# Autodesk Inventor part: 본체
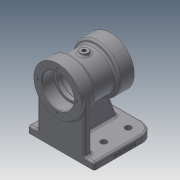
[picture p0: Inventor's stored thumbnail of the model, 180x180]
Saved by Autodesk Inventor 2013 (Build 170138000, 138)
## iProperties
Created: 2020-06
Part Number: 본체
Material: 일반
Document SubType Name: Modeling
Designer: 19
Density: 1 g/cm^3
Mass: 268.673 g
Surface Area: 641.499 cm^2
Volume: 268.673 cm^3
Author: 19
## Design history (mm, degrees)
sketch "스케치2"
  geometry: C1 r 35 at (0, 0); 1 further point
  constraints: 1 centre point, 1 coincident
  dimensions: "d8" = 70 diameter of C1
extrude "돌출1" new body sketch "스케치2" distance "d10" = 22; taper "d11" = 0 deg
sketch "스케치3"
  geometry: C1 r 35 at (0, 0) reference; C2 r 29 at (0, 0)
  constraints: 1 centre point, 1 coincident
  dimensions: "d12" = 29 radius of C2
extrude "돌출2" join sketch "스케치3" distance "d13" = 34; taper "d14" = 0 deg
sketch "스케치4"
  geometry: C1 r 29 at (0, 0) reference; C2 r 35 at (0, 0)
  constraints: 1 centre point, 1 coincident
  dimensions: "d15" = 35 radius of C2
extrude "돌출3" join sketch "스케치4" distance "d16" = 22; taper "d17" = 0 deg
sketch "스케치5"
  geometry: C1 r 35 at (0, 0) reference; C2 r 23.5 at (0, 0)
  constraints: 1 centre point, 1 coincident
  dimensions: "d18" = 47 diameter of C2
extrude "돌출4" cut sketch "스케치5" distance "d20" = 18; taper "d21" = 0 deg
sketch "스케치6"
  geometry: C1 r 23.5 at (0, 0) reference; C2 r 20 at (0, 0)
  constraints: 1 centre point, 1 coincident
  dimensions: "d22" = 20 radius of C2
extrude "돌출5" cut sketch "스케치6" distance "d23" = 6; taper "d24" = 0 deg
sketch "스케치7"
  geometry: C1 r 20 at (0, 0) reference; C2 r 23 at (0, 0)
  constraints: 1 centre point, 1 coincident
  dimensions: "d25" = 46 diameter of C2
extrude "돌출6" cut sketch "스케치7" distance "d27" = 30; taper "d28" = 0 deg
sketch "스케치8"
  geometry: C1 r 35 at (0, 0) reference; C2 r 23.5 at (0, 0)
  constraints: 1 centre point, 1 coincident
  dimensions: "d29" = 47 diameter of C2
extrude "돌출7" cut sketch "스케치8" distance "d31" = 18; taper "d32" = 0 deg
sketch "스케치9"
  geometry: C1 r 23.5 at (0, 0) reference; C2 r 20 at (0, 0)
  constraints: 1 centre point, 1 coincident
  dimensions: "d33" = 20 radius of C2
extrude "돌출8" cut sketch "스케치9" distance "d34" = 6; taper "d35" = 0 deg
node "작업 평면2"
  node "작업 평면1"
sketch "스케치10"
  geometry: L1 (14.177, 34)-(-14.177, 34) reference; L2 (-14.177, 34)-(-14.177, 56) reference; L3 (-14.177, 56)-(14.177, 56) reference; L4 (14.177, 56)-(14.177, 34) reference; L5 (-14.177, -22)-(-14.177, 0) reference; L6 (-14.177, 0)-(14.177, 0) reference; L7 (14.177, 0)-(14.177, -22) reference; L8 (14.177, -22)-(-14.177, -22) reference; C1 r 6 at (0, 17); 2 further points
  constraints: 1 centre point, 1 midpoint, 1 vertical alignment
  dimensions: "d41" = 12 diameter of C1; "d42" = 39 distance from line of L3 C1.centre
extrude "돌출9" join sketch "스케치10" stored distance "d43" = 3; taper "d44" = 0 deg
sketch "스케치11"
  geometry: C1 r 6 at (0, 0) reference; 1 further point
hole "구멍1" sketch "스케치11" at (0, 0) diameter "d45" = 5.188; stored, may be unused: countersink angle "d49" = 90 deg, drill point angle "d51" = 118 deg; dims "d46" = 30, "d47" = 4, "d48" = 2, "d50" = 8
node "작업 평면3"
sketch "스케치12"
  geometry: L1 (49, 73)-(-49, 73); L2 (-49, 73)-(-49, -17); L3 (-49, -17)-(49, -17); L4 (49, -17)-(49, 73); L5 (35, 78)-(-35, 78) reference; L6 (-35, 0)-(35, 0) reference; 5 further points
  constraints: 8 end point, 4 midpoint, 2 parallel, 2 vertical alignment, 1 horizontal, 1 perpendicular
  dimensions: "d53" = 5 distance between parallel lines of L1 L5; "d54" = 90 distance of L3.end L1.start; "d55" = 98 distance of L2.end L3.end
extrude "돌출10" join sketch "스케치12" distance "d56" = 10; taper "d57" = 0 deg
sketch "스케치13"
  geometry: L1 (-49, -73)-(49, -73) reference; L2 (-35, -63)-(35, -63); L3 (35, -63)-(35, -73); L4 (35, -73)-(-35, -73); L5 (-35, -73)-(-35, -63); 3 further points
  constraints: 8 end point, 3 midpoint, 2 parallel, 1 horizontal, 1 perpendicular, 1 vertical alignment
  dimensions: "d58" = 10 distance of L2.end L3.end; "d60" = 70 distance of L2.start L2.end
extrude "돌출11" join sketch "스케치13" stored distance "d61" = 10; taper "d62" = 0 deg
sketch "스케치14"
  geometry: L1 (-35, -63)-(35, -63) reference; L2 (49, 17)-(-49, 17) reference; L3 (-5, 5)-(5, 5); L4 (5, 5)-(5, -63); L5 (5, -63)-(-5, -63); L6 (-5, -63)-(-5, 5); 3 further points
  constraints: 8 end point, 3 midpoint, 2 parallel, 1 horizontal, 1 perpendicular, 1 vertical alignment
  dimensions: "d63" = 12 distance between parallel lines of L3 L2; "d64" = 10 distance of L3.start L3.end
extrude "돌출12" join sketch "스케치14" stored distance "d66" = 10; taper "d67" = 0 deg
feature "면 기울기1" dims angle "d68" = 20 deg
sketch "스케치15"
  geometry: L1 (0, 28.5)-(0, 0); L2 (0, 0)-(28.5, 0); L3 (-28.5, 0)-(0, 0); L4 (0, -28.5)-(0, 0); C1 r 35 at (0, 0) reference; A1 r 28.5 centre (0, 0) between (0, 28.5) and (28.5, 0)
  constraints: 8 end point, 4 point on circle, 2 perpendicular, 1 centre point, 1 coincident, 1 collinear, 1 vertical
  dimensions: "d69" = 57 diameter of A1
hole "구멍2" sketch "스케치15" at (0, 28.5), (28.5, 0), (-28.5, 0), (0, -28.5) diameter "d71" = 3.242; stored, may be unused: countersink angle "d75" = 90 deg, drill point angle "d77" = 118 deg; dims "d72" = 10, "d73" = 4, "d74" = 2, "d76" = 12
sketch "스케치16"
  geometry: L1 (0, 0)-(0, 28.5); L2 (0, 0)-(28.5, 0); L3 (0, 0)-(0, -28.5); L4 (0, 0)-(-28.5, 0); C1 r 23.5 at (0, 0) reference; A1 r 28.5 centre (0, 0) between (0, 28.5) and (28.5, 0)
  constraints: 8 end point, 4 point on circle, 3 perpendicular, 1 centre point, 1 coincident, 1 vertical
  dimensions: "d78" = 57 diameter of A1
hole "구멍3" sketch "스케치16" at (0, 28.5), (28.5, 0), (0, -28.5), (-28.5, 0) diameter "d80" = 3.242; stored, may be unused: countersink angle "d84" = 90 deg, drill point angle "d86" = 118 deg; dims "d81" = 10, "d82" = 4, "d83" = 2, "d85" = 12
sketch "스케치18"
  geometry: L1 (0, 0)-(90, 0) reference; L2 (0, 0)-(0, 10) reference; 2 further points
  constraints: 1 other
  dimensions: "d87" = 4 distance from line of L1 point (45, 4); "d88" = 45 distance from line of point (45, 4) L2
feature "엠보싱1" sketch "스케치18" dims "d8" = 70, "d89" = 0.5, "d90" = 0
chamfer "모따기1" distance "d91" = 1; stored, may be unused: second distance "d92" = 2, angle "d93" = 45 deg
fillet "모깎기1" dims "d94" = 0.3
fillet "모깎기2" dims "d95" = 3
fillet "모깎기3" dims "d96" = 3
fillet "모깎기4" dims "d97" = 3
fillet "모깎기5" dims "d98" = 3
fillet "모깎기6" dims "d99" = 20
fillet "모깎기7" dims "d100" = 3
fillet "모깎기8" dims "d101" = 3
fillet "모깎기9" dims "d102" = 3
fillet "모깎기10" dims "d103" = 3
fillet "모깎기11" dims "d104" = 3
fillet "모깎기12" dims "d105" = 3
sketch "스케치19"
  geometry: L1 (-46, -70)-(-46, -3) reference; L2 (-29, -3)-(-29, -39); L3 (29, -3)-(29, -39); C1 r 4.5 at (-29, -3); C2 r 4.5 at (29, -3); C3 r 4.5 at (-29, -39); C4 r 4.5 at (29, -39); A1 r 17 centre (29, -3) between (46, -3) and (29, 14) reference; A2 r 17 centre (-29, -3) between (-29, 14) and (-46, -3) reference; 1 further point
  constraints: 4 centre point, 4 coincident, 4 end point, 2 parallel
  dimensions: "d106" = 4.5 radius of C1; "d107" = 4.5 radius of C2; "d108" = 36 distance of L2.start L2.end; "d109" = 36 distance of L3.start L3.end; "d110" = 4.5 radius of C3; "d111" = 4.5 radius of C4
extrude "돌출13" cut sketch "스케치19" stored distance "d112" = 9; taper "d113" = 0 deg
node "솔리드1"
node "절단 모서리 투영1"
other parameters: "d36" = 3
